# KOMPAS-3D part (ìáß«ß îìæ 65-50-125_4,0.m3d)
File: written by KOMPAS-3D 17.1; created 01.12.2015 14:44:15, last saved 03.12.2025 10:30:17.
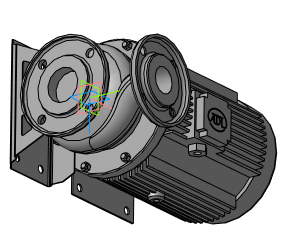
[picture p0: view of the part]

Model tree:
1. Операция без истории:3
